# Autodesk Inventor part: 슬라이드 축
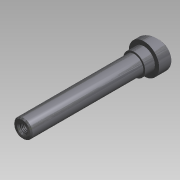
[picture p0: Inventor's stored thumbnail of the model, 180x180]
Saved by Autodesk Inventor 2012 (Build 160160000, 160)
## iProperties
Created: 2012-05
Part Number: 슬라이드 축
Document SubType Name: 모델링
Designer: SeoGD™
Mass: 169.556 g
Surface Area: 67.5855 cm^2
Volume: 21.572 cm^3
Density: 7.86 g/cm^3
Material: 강, 연강
변환 표준: STEP AP214IS
파일 이름: C:\Users\SeoGD\Desktop\?쒗뿕\異?stp
전처리기: Build: 253, Release: 2010 SP1 - Date: Wed 07/29/2009
전송 단위: 밀리미터
불확실성: 0.01
Author: SeoGD™
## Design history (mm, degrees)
sketch "스케치1"
  geometry: L1 (0, 100)-(7.5, 100); L2 (7.5, 100)-(7.5, 0); L3 (7.5, 0)-(12.5, 0); L4 (12.5, 0)-(12.5, -17); L5 (12.5, -17)-(0, -17); L6 (0, -17)-(0, 100); 1 further point
  constraints: 12 end point, 2 parallel, 2 point on line, 1 perpendicular, 1 vertical
  dimensions: "d0" = 100 distance from line of L1 point (0, 0); "d1" = 15 diameter of L2 L6; "d2" = 25 diameter of L4 L6; "d3" = 17 distance of L3.end L4.end
revolve "회전1" sketch "스케치1" stored, may be unused: angle "d4" = 90 deg
sketch "스케치2"
  geometry: L1 (12.5, 0)-(12.5, -17) reference; L2 (-12.5, -17)-(12.5, -17) reference; L3 (-12.5, 0)-(-12.5, -17) reference; L4 (12.5, -5)-(-12.5, -11.699); L5 (-12.5, 0)-(12.5, 0) reference; 1 further point
  constraints: 2 end point, 2 point on line
  dimensions: "d5" = 75 deg angle of L1 L4; "d6" = 5 distance from line of L4.start L5
extrude "돌출1" cut sketch "스케치2" stored distance "d7" = 10; taper "d8" = 0 deg
chamfer "모따기1" distance "d9" = 1; stored, may be unused: second distance "d10" = 2, angle "d11" = 45 deg
fillet "모깎기1" dims "d12" = 0.5
hole "구멍1" diameter "d15" = 6.647; stored, may be unused: countersink angle "d19" = 90 deg, drill point angle "d21" = 118 deg; dims "d13" = 10, "d14" = 10, "d16" = 17, "d17" = 4, "d18" = 2, "d20" = 20
chamfer "모따기2" distance "d22" = 1; stored, may be unused: second distance "d23" = 2, angle "d24" = 45 deg
sketch "스케치3"
  geometry: C1 r 9 at (0, 0); 1 further point
  constraints: 1 centre point, 1 coincident
  dimensions: "d25" = 18 diameter of C1
extrude "돌출2" join sketch "스케치3" distance "d26" = 8; taper "d27" = 0 deg
node "솔리드1"
node "솔리드 본체"
node "곡면 본체"
node "솔리드2"
